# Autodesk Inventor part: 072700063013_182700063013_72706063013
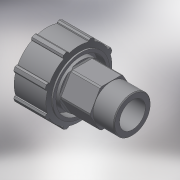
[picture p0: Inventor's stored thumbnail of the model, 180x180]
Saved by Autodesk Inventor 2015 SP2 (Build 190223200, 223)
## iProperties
Created: 2017-04
Part Number: 072700063013_182700063013_72706063013
Material: Generic
Description: PLASSON BRASS THREADED ADAPTOR 63-1.1/4"
Document SubType Name: Modeling
Designer: KIM
Density: 1 g/cm^3
Appearance: Default
Author: KIM
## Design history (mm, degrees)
derived "07270.ipt"
feature "Solid1::07270.ipt"
tag "TaggingFeature1"
body "Solid1"
other parameters: "d1" = 41.91, "d2" = 105, "d3" = 21, "d7" = 113, "d8" = 90.4, "d9" = 63, "d12" = 29.337, "d13" = 33.528, "d15" = 84.75, "d17" = 42, "d18" = 21, "d19" = 25.2, "d40" = 64, "d41" = 73.6, "d42" = 135 deg, "d43" = 100 deg, "d44" = 38.64, "d45" = 80.5125, "d46" = 105.09, "d47" = 35 deg, "d48" = 17.5 deg, "d50" = 0, "d52" = 360 deg, "d54" = 2.26, "d57" = 2.26, "d61" = 0, "d62" = 0.8382, "d65" = 1.2573, "d_" = 63, "R_" = 41.91, "E_" = 113, "H_" = 105, "l_2" = 21, "Wrench" = 64
